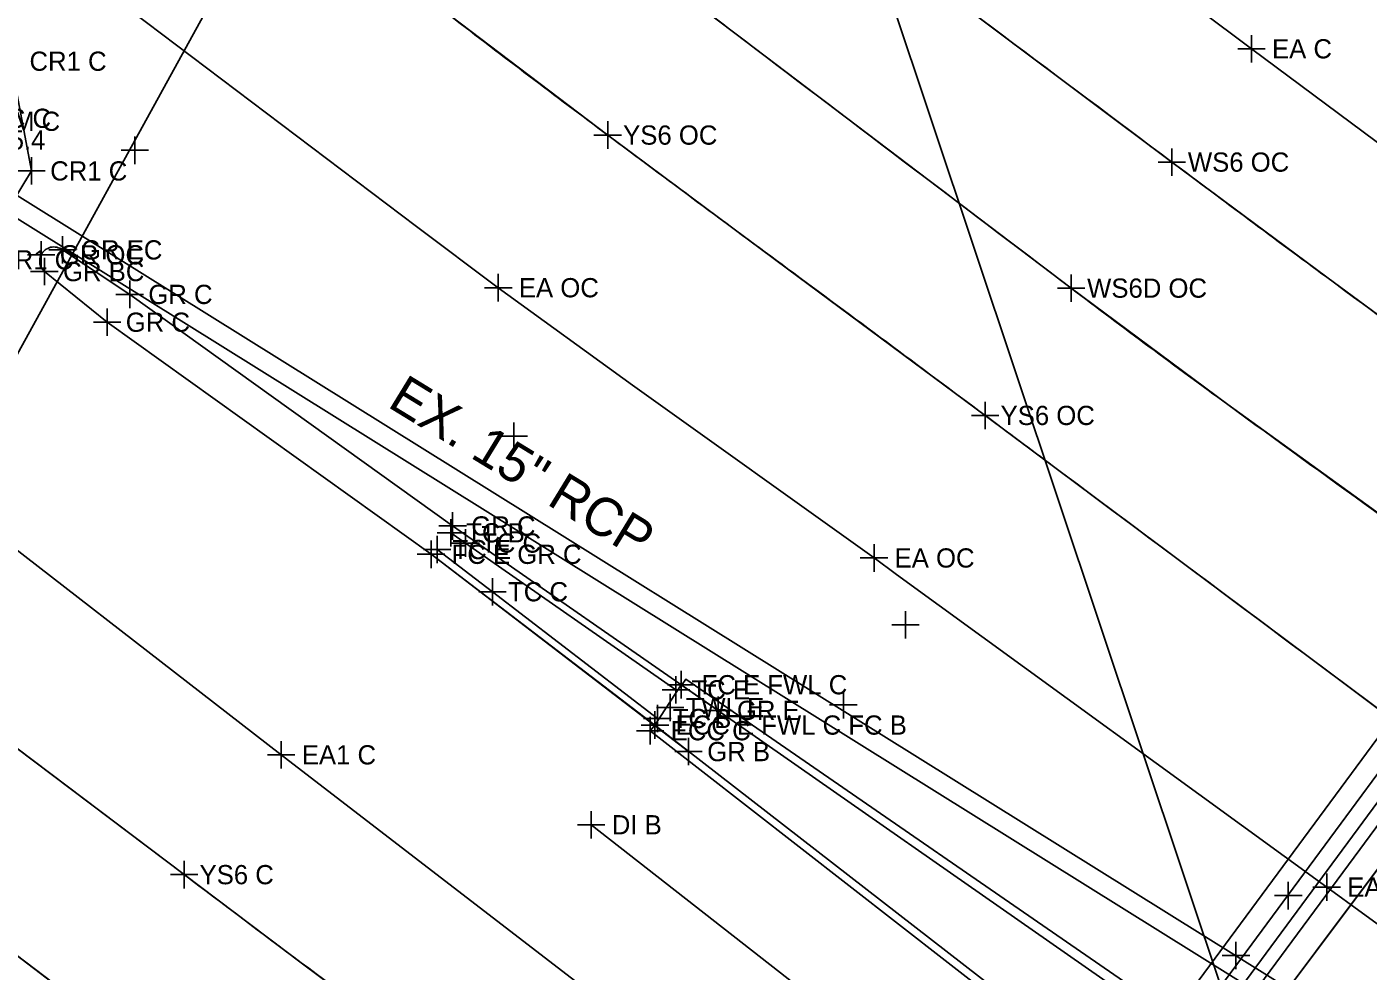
# Model space of a CAD drawing. Extents: x 1324236 to 1326110, y 459090 to 460782.
# Drawn here: x 1325040 to 1325137.7, y 460070.9 to 460139.7 of the extents above; entities that cross this region are included whole.
import ezdxf

# ---------------------------------------------------------------- set-up
doc = ezdxf.new("R2010")
doc.units = 0
for name, color, linetype in [('BD_X_Building', 7, 'Continuous'), ('BD_X_Canopy', 7, 'Continuous'), ('DR_X_Ditch', 7, 'Continuous'), ('DR_X_Drive_Pipe', 7, 'Continuous'), ('DT_X_Contour_Text', 7, 'Continuous'), ('DT_X_Island', 7, 'Continuous'), ('DT_X_Terrain_Boundary', 7, 'Continuous'), ('DV_X_Property_Line', 7, 'Continuous'), ('E-RW-ODOT', 7, 'Continuous'), ('PM_X_Edge_Line', 7, 'Continuous'), ('PM_X_Lane_Line', 7, 'Continuous'), ('PM_X_Misc', 7, 'Continuous'), ('PV_X_Shoulder', 7, 'Continuous'), ('RW_X_CL', 7, 'Continuous'), ('RW_X_Esmt_SH', 7, 'Continuous'), ('UT_X_Gas', 7, 'Continuous'), ('UT_X_Telecom', 7, 'Continuous'), ('VG_X_Flower_Bed', 7, 'Continuous')]:
    doc.layers.add(name, color=color, linetype=linetype)

msp = doc.modelspace()

# ---------------------------------------------------------------- linework, layer by layer
at = {"layer": 'BD_X_Building'}
for p, q in [((1325052.458, 459966.873), (1325198.712, 460164.842)), ((1325053.263, 459966.279), (1325199.516, 460164.248))]:
    msp.add_line(p, q, dxfattribs=at)
at = {"layer": 'BD_X_Canopy'}
for points in [[(1324857.991, 460211.284), (1324902.588, 460176.578), (1324902.588, 460176.578), (1324936.62, 460150.139), (1324936.62, 460150.139), (1324961.591, 460130.759), (1324961.663, 460130.703), (1324961.663, 460130.703), (1324972.924, 460122.216), (1324972.924, 460122.216), (1324989.955, 460109.491), (1324989.955, 460109.491), (1325006.286, 460097.056), (1325006.286, 460097.056), (1325017.201, 460088.752), (1325017.201, 460088.752), (1325017.437, 460088.573), (1325017.437, 460088.573), (1325043.951, 460068.47), (1325052.569, 460061.944), (1325052.569, 460061.944), (1325070.018, 460048.758), (1325070.018, 460048.758), (1325098.234, 460028.131)], [(1325148.737, 460096.817), (1325127.476, 460112.152), (1325127.476, 460112.152), (1325116.067, 460120.628), (1325116.067, 460120.628), (1325091.576, 460139.19), (1325091.576, 460139.19), (1325088.482, 460141.518), (1325088.482, 460141.518), (1325074.633, 460151.849), (1325074.633, 460151.849), (1325061.29, 460161.8), (1325061.29, 460161.8), (1325040.713, 460177.132), (1325040.713, 460177.132), (1325034.153, 460182.028)]]:
    msp.add_lwpolyline(points, dxfattribs=at)
at = {"layer": 'DR_X_Ditch'}
for points in [[(1325155.492, 460106.108), (1325134.695, 460121.415), (1325134.695, 460121.415), (1325123.409, 460129.807), (1325123.409, 460129.807), (1325098.919, 460148.148), (1325098.919, 460148.148), (1325096.464, 460149.982), (1325096.464, 460149.982), (1325083.308, 460159.732), (1325083.308, 460159.732), (1325068.254, 460170.882), (1325068.254, 460170.882), (1325049.774, 460184.674), (1325049.774, 460184.674), (1325042.007, 460190.543), (1325042.007, 460190.543), (1325032.409, 460197.885)], [(1325154.473, 460078.072), (1325145.108, 460085.017), (1325145.108, 460085.017), (1325142.611, 460086.875), (1325142.611, 460086.875), (1325114.786, 460107.642), (1325114.786, 460107.642), (1325109.805, 460111.357), (1325109.805, 460111.357), (1325095.416, 460122.039), (1325095.416, 460122.039), (1325082.306, 460131.775), (1325082.306, 460131.775), (1325070.853, 460140.451), (1325070.853, 460140.451), (1325055.079, 460152.45), (1325055.079, 460152.45), (1325039.723, 460163.871)], [(1325024.569, 460098.191), (1325051.446, 460077.913), (1325059.985, 460071.501), (1325059.985, 460071.501), (1325077.437, 460058.485), (1325077.437, 460058.485), (1325105.01, 460038.085)]]:
    msp.add_lwpolyline(points, dxfattribs=at)
at = {"layer": 'DR_X_Drive_Pipe'}
msp.add_line((1325081.105, 460081.547), (1325116.434, 460053.941), dxfattribs=at)
at = {"layer": 'DT_X_Contour_Text'}
msp.add_line((1325140.597, 460088.248), (1325125.374, 460067.638), dxfattribs=at)
at = {"layer": 'DT_X_Island'}
for p, q in [((1325038.824, 460137.155), (1325040.331, 460129.164)), ((1325040.331, 460129.164), (1325036.392, 460122.692))]:
    msp.add_line(p, q, dxfattribs=at)
msp.add_lwpolyline([(1325032.678, 460144.91), (1325038.824, 460137.155), (1325040.331, 460129.164), (1325036.392, 460122.692), (1325030.716, 460119.144), (1325021.275, 460122.094)], dxfattribs=at)
at = {"layer": 'DT_X_Terrain_Boundary'}
for p, q in [((1325070.874, 460102.809), (1325071.957, 460102.063)), ((1325085.752, 460088.809), (1325069.434, 460101.243)), ((1325073.921, 460098.517), (1325069.878, 460101.589)), ((1325071.957, 460102.063), (1325087.28, 460091.376)), ((1325085.923, 460089.286), (1325073.921, 460098.517)), ((1325085.752, 460088.809), (1325087.651, 460091.746)), ((1325087.651, 460091.746), (1325121.168, 460068.372)), ((1325085.397, 460088.397), (1325085.752, 460088.809)), ((1325118.274, 460063.58), (1325085.752, 460088.809)), ((1325120.636, 460060.99), (1325085.397, 460088.397))]:
    msp.add_line(p, q, dxfattribs=at)
msp.add_lwpolyline([(1325184.337, 460020.14), (1325184.771, 460020.802), (1325175.691, 460027.851), (1325149.757, 460048.271), (1325124.75, 460066.799), (1325087.999, 460092.157), (1325087.726, 460091.756)], dxfattribs=at)
at = {"layer": 'DV_X_Property_Line'}
for p, q in [((1325129.205, 460137.057), (1325129.205, 460139.057)), ((1325128.205, 460138.057), (1325130.205, 460138.057)), ((1325074.335, 460119.659), (1325074.335, 460121.659)), ((1325073.335, 460120.659), (1325075.335, 460120.659)), ((1325070.874, 460101.809), (1325070.874, 460103.809)), ((1325069.434, 460100.243), (1325069.434, 460102.243)), ((1325069.874, 460102.809), (1325071.874, 460102.809)), ((1325069.878, 460100.589), (1325069.878, 460102.589)), ((1325071.957, 460101.063), (1325071.957, 460103.063)), ((1325068.434, 460101.243), (1325070.434, 460101.243)), ((1325068.878, 460101.589), (1325070.878, 460101.589)), ((1325070.957, 460102.063), (1325072.957, 460102.063)), ((1325101.709, 460099.976), (1325101.709, 460101.976)), ((1325100.709, 460100.976), (1325102.709, 460100.976)), ((1325073.921, 460097.517), (1325073.921, 460099.517)), ((1325072.921, 460098.517), (1325074.921, 460098.517)), ((1325087.651, 460090.746), (1325087.651, 460092.746)), ((1325086.651, 460091.746), (1325088.651, 460091.746)), ((1325087.28, 460090.376), (1325087.28, 460092.376)), ((1325086.28, 460091.376), (1325088.28, 460091.376)), ((1325086.861, 460089.081), (1325086.861, 460091.081)), ((1325085.752, 460087.809), (1325085.752, 460089.809)), ((1325085.861, 460090.081), (1325087.861, 460090.081)), ((1325085.923, 460088.286), (1325085.923, 460090.286)), ((1325084.752, 460088.809), (1325086.752, 460088.809)), ((1325084.923, 460089.286), (1325086.923, 460089.286)), ((1325085.397, 460087.397), (1325085.397, 460089.397)), ((1325058.52, 460085.639), (1325058.52, 460087.639)), ((1325084.397, 460088.397), (1325086.397, 460088.397)), ((1325057.52, 460086.639), (1325059.52, 460086.639)), ((1325134.688, 460076.008), (1325134.688, 460078.008)), ((1325133.688, 460077.008), (1325135.688, 460077.008))]:
    msp.add_line(p, q, dxfattribs=at)
at = {"layer": 'E-RW-ODOT'}
for p, q in [((1325006.97, 460057.154), (1325084.273, 460197.503)), ((1325084.273, 460197.503), (1325176.946, 459920.265)), ((1325176.946, 459920.265), (1325084.273, 460197.503))]:
    msp.add_line(p, q, dxfattribs=at)
at = {"layer": 'PM_X_Edge_Line'}
for p, q in [((1325024.569, 460098.191), (1325051.446, 460077.913)), ((1325144.058, 460085.869), (1325128.817, 460065.555))]:
    msp.add_line(p, q, dxfattribs=at)
msp.add_lwpolyline([(1325201.35, 460162.951), (1325188.112, 460145.092), (1325173.118, 460124.971), (1325158.515, 460105.214), (1325144.058, 460085.869), (1325128.817, 460065.555), (1325114.8, 460046.648), (1325099.946, 460026.52), (1325084.688, 460005.952), (1325070.054, 459986.286), (1325054.62, 459965.363)], dxfattribs=at)
for centre, radius, start, end in [((1386161.743, 541657.975), 101845.571, 233.16140248, 233.17861513), ((1325667.685, 460916.457), 978.976, 232.435845, 233.276758), ((1327349.666, 463171.097), 3791.886, 233.276758, 233.523491), ((1326432.383, 461878.188), 2184.089, 233.178615, 233.547566), ((1322380.157, 456449.43), 4567.35, 53.298677, 53.523491), ((1329509.495, 466043.894), 7363.059, 233.5475656, 233.7485089), ((1319352.658, 452387.925), 9633.076, 53.2617146, 53.2986775), ((1504988.507, 701090.54), 300711.345, 233.26171632, 233.26833173), ((1326494.271, 461990.305), 2395.618, 232.966881, 233.222271), ((1331022.284, 468047.933), 9958.538, 233.2222711, 233.3475318)]:
    msp.add_arc(centre, radius, start, end, dxfattribs=at)
at = {"layer": 'PM_X_Lane_Line'}
msp.add_line((1325017.437, 460088.573), (1325043.951, 460068.47), dxfattribs=at)
for centre, radius, start, end in [((1324803.591, 459759.643), 476.436, 52.81022, 53.27586), ((1343231.876, 484047.003), 30010.897, 232.8102157, 232.8688853), ((1325585.849, 460741.09), 778.248, 232.868885, 233.915284), ((1326686.695, 462251.573), 2647.316, 233.915284, 234.482631)]:
    msp.add_arc(centre, radius, start, end, dxfattribs=at)
at = {"layer": 'PM_X_Misc'}
for p, q in [((1325042.579, 460123.413), (1325047.481, 460120.172)), ((1325045.838, 460118.147), (1325041.265, 460121.834)), ((1325047.481, 460120.172), (1325071.01, 460103.308)), ((1325069.434, 460101.243), (1325045.838, 460118.147)), ((1325071.01, 460103.308), (1325090.365, 460089.877)), ((1325088.2, 460086.876), (1325069.434, 460101.243))]:
    msp.add_line(p, q, dxfattribs=at)
for start, end in [(153.5931, 228.08751), (52.37991, 153.5931)]:
    msp.add_arc((1325041.952, 460122.599), 1.028, start, end, dxfattribs=at)
at = {"layer": 'PV_X_Shoulder'}
for points in [[(1324669.977, 460389.307), (1324715.857, 460353.853), (1324792.73, 460293.173), (1324872.956, 460231.134), (1324952.761, 460169.097), (1324978.518, 460148.785), (1325005.245, 460128.104), (1325032.046, 460107.124), (1325058.52, 460086.639), (1325084.001, 460067.05), (1325111.268, 460046.593)], [(1325158.979, 460120.559), (1325156.362, 460117.885), (1325129.205, 460138.057), (1325101.695, 460158.661), (1325088.736, 460168.391), (1325089.903, 460170.124), (1325075.664, 460180.539), (1325048.93, 460200.83), (1325022.038, 460221.255), (1324994.584, 460242.451), (1324967.703, 460263.248), (1324940.215, 460284.329), (1324913.588, 460305.261), (1324886.1, 460326.42), (1324858.748, 460347.833)], [(1325146.82, 460068.183), (1325137.288, 460075.117), (1325137.288, 460075.117), (1325134.688, 460077.008), (1325134.688, 460077.008), (1325103.35, 460099.784), (1325101.709, 460100.976), (1325101.709, 460100.976), (1325084.12, 460113.571), (1325084.12, 460113.571), (1325074.335, 460120.659), (1325074.335, 460120.659), (1325068.382, 460125.119), (1325068.382, 460125.119), (1325046.512, 460141.658), (1325046.512, 460141.658), (1325023.806, 460158.868)]]:
    msp.add_lwpolyline(points, dxfattribs=at)
at = {"layer": 'RW_X_CL'}
for p, q in [((1325082.306, 460130.775), (1325082.306, 460132.775)), ((1325047.861, 460129.667), (1325047.861, 460131.667)), ((1325081.306, 460131.775), (1325083.306, 460131.775)), ((1325046.861, 460130.667), (1325048.861, 460130.667)), ((1325123.409, 460128.807), (1325123.409, 460130.807)), ((1325040.331, 460128.164), (1325040.331, 460130.164)), ((1325122.409, 460129.807), (1325124.409, 460129.807)), ((1325039.331, 460129.164), (1325041.331, 460129.164)), ((1325116.067, 460119.628), (1325116.067, 460121.628)), ((1325115.067, 460120.628), (1325117.067, 460120.628)), ((1325109.805, 460110.357), (1325109.805, 460112.357)), ((1325108.805, 460111.357), (1325110.805, 460111.357)), ((1325075.467, 460108.835), (1325075.467, 460110.835)), ((1325074.467, 460109.835), (1325076.467, 460109.835)), ((1325104.003, 460095.111), (1325104.003, 460097.111)), ((1325103.003, 460096.111), (1325105.003, 460096.111)), ((1325099.475, 460089.292), (1325099.475, 460091.292)), ((1325098.475, 460090.292), (1325100.475, 460090.292)), ((1325051.446, 460076.913), (1325051.446, 460078.913)), ((1325050.446, 460077.913), (1325052.446, 460077.913)), ((1325131.89, 460075.384), (1325131.89, 460077.384)), ((1325130.89, 460076.384), (1325132.89, 460076.384)), ((1325128.077, 460071.028), (1325128.077, 460073.028)), ((1325127.077, 460072.028), (1325129.077, 460072.028))]:
    msp.add_line(p, q, dxfattribs=at)
at = {"layer": 'RW_X_Esmt_SH'}
for p, q in [((1325041.031, 460122.056), (1325041.031, 460124.056)), ((1325042.579, 460122.413), (1325042.579, 460124.413)), ((1325040.031, 460123.056), (1325042.031, 460123.056)), ((1325041.265, 460120.834), (1325041.265, 460122.834)), ((1325041.579, 460123.413), (1325043.579, 460123.413)), ((1325040.265, 460121.834), (1325042.265, 460121.834)), ((1325047.481, 460119.172), (1325047.481, 460121.172)), ((1325046.481, 460120.172), (1325048.481, 460120.172)), ((1325045.838, 460117.147), (1325045.838, 460119.147)), ((1325044.838, 460118.147), (1325046.838, 460118.147)), ((1325071.01, 460102.308), (1325071.01, 460104.308)), ((1325070.01, 460103.308), (1325072.01, 460103.308)), ((1325090.365, 460088.877), (1325090.365, 460090.877)), ((1325089.365, 460089.877), (1325091.365, 460089.877)), ((1325088.2, 460085.876), (1325088.2, 460087.876)), ((1325087.2, 460086.876), (1325089.2, 460086.876)), ((1325081.105, 460080.547), (1325081.105, 460082.547)), ((1325080.105, 460081.547), (1325082.105, 460081.547))]:
    msp.add_line(p, q, dxfattribs=at)
at = {"layer": 'UT_X_Gas'}
msp.add_line((1325196.49, 460166.476), (1325050.21, 459968.526), dxfattribs=at)
at = {"layer": 'VG_X_Flower_Bed'}
for p, q in [((1325179.267, 460040.1), (1325032.782, 460131.415)), ((1325178.666, 460038.796), (1325032.157, 460130.12))]:
    msp.add_line(p, q, dxfattribs=at)

# ---------------------------------------------------------------- texts
at = {"layer": 'DV_X_Property_Line'}
for s, p in [('EA C', (1325130.705, 460137.357)), ('CSTM C', (1325035.241, 460132.08)), ('ECC C', (1325035.929, 460132.297)), ('EA OC', (1325075.835, 460119.959)), ('TC B', (1325071.999, 460102.109)), ('TC E', (1325071.003, 460100.889)), ('TC C', (1325073.082, 460101.363)), ('FC E GR C', (1325070.934, 460100.543)), ('EA OC', (1325103.209, 460100.276)), ('TC C', (1325075.046, 460097.817)), ('FC E FWL C', (1325089.151, 460091.046)), ('TC E', (1325088.405, 460090.676)), ('TWL E', (1325087.986, 460089.381)), ('TC B', (1325087.048, 460088.586)), ('ECC E FWL C FC B', (1325087.252, 460088.109)), ('ECC C', (1325086.897, 460087.697)), ('EA1 C', (1325060.02, 460085.939)), ('EA OC', (1325136.188, 460076.308))]:
    msp.add_text(s, height=1.4, dxfattribs=at).set_placement(p)
at = {"layer": 'RW_X_CL'}
for s, p in [('CR1 C', (1325040.181, 460136.455)), ('CB3.1X5.4', (1325032.286, 460130.722)), ('YS6 OC', (1325083.431, 460131.075)), ('CR1 C', (1325041.688, 460128.464)), ('WS6 OC', (1325124.576, 460129.107)), ('CR1 C', (1325037.749, 460121.992)), ('WS6D OC', (1325117.233, 460119.928)), ('YS6 OC', (1325110.93, 460110.657)), ('YS6 C', (1325052.571, 460077.213))]:
    msp.add_text(s, height=1.4, dxfattribs=at).set_placement(p)
at = {"layer": 'RW_X_Esmt_SH'}
for s, p in [('GR OC', (1325042.388, 460122.356)), ('GR EC', (1325043.936, 460122.713)), ('GR BC', (1325042.622, 460121.134)), ('GR C', (1325048.838, 460119.472)), ('GR C', (1325047.195, 460117.447)), ('GR C', (1325072.367, 460102.608)), ('GR E', (1325091.722, 460089.177)), ('GR B', (1325089.557, 460086.176)), ('DI B', (1325082.605, 460080.847))]:
    msp.add_text(s, height=1.4, dxfattribs=at).set_placement(p)
at = {"layer": 'UT_X_Telecom'}
msp.add_text('EX. 15" RCP', height=2.79999, rotation=328.54198, dxfattribs=at).set_placement((1325066.181, 460112.031))

doc.saveas('drawing.dxf')
